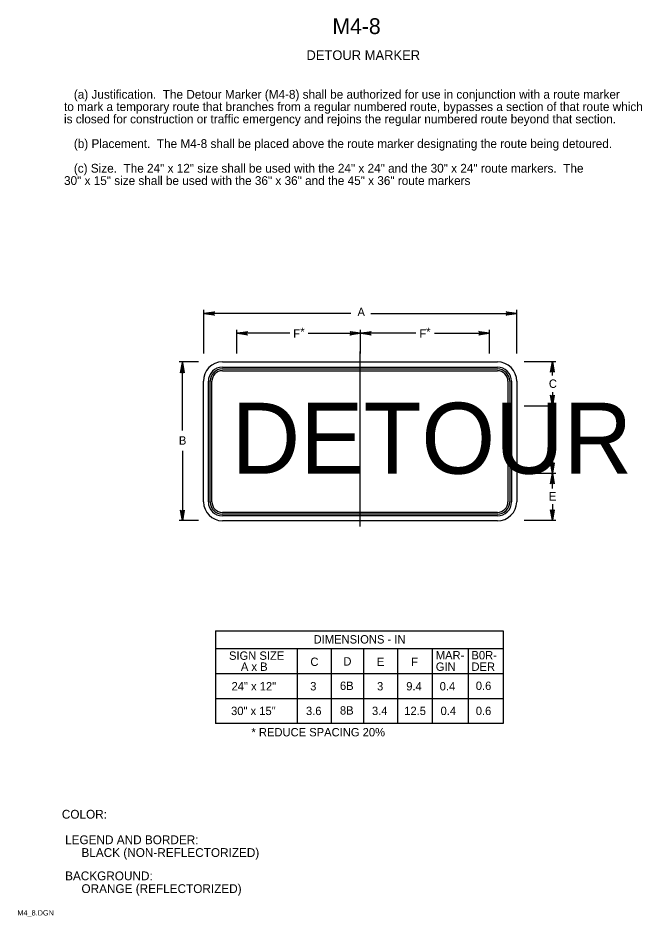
# Model space of a CAD drawing. Extents: x 0.013 to 0.19, y 0.004 to 0.259.
import ezdxf

# ---------------------------------------------------------------- set-up
doc = ezdxf.new("R2010")
doc.units = 0
for name, color, linetype in [('1', 7, 'Continuous'), ('2', 7, 'Continuous'), ('3', 7, 'Continuous')]:
    doc.layers.add(name, color=color, linetype=linetype)

# ---------------------------------------------------------------- blocks, each defined once
blk = doc.blocks.new('RARROW')
at = {"layer": '3'}
for p, q in [((-2.156, 0.285), (-2.2665, 0.384625)), ((-2.2665, 0.384625), (0, 0)), ((0, 0), (-2.2665, -0.379125)), ((-2.156, 0.285), (-2.075625, 0.12075)), ((0, 0), (-2.156, 0.285)), ((-2.14975, -0.2705), (0, 0)), ((-2.075625, 0.12075), (0, 0)), ((0, 0), (-2.074, -0.108)), ((-2.2665, -0.379125), (-2.14975, -0.2705)), ((-2.074, -0.108), (-2.14975, -0.2705))]:
    blk.add_line(p, q, dxfattribs=at)

msp = doc.modelspace()

# ---------------------------------------------------------------- linework, layer by layer
at = {"layer": '3'}
for p, q in [((0.0655, 0.16402), (0.0655, 0.17638)), ((0.15438, 0.16402), (0.15438, 0.17638)), ((0.10725, 0.17538), (0.0655, 0.17538)), ((0.11288, 0.17538), (0.15438, 0.17538)), ((0.07487, 0.16402), (0.07487, 0.17075)), ((0.08987, 0.16975), (0.07487, 0.16975)), ((0.09513, 0.16975), (0.11, 0.16975)), ((0.11, 0.16402), (0.11, 0.17075)), ((0.12575, 0.16975), (0.11, 0.16975)), ((0.131, 0.16975), (0.14663, 0.16975)), ((0.14663, 0.16402), (0.14663, 0.17075)), ((0.10988, 0.11488), (0.10988, 0.16462)), ((0.064, 0.16162), (0.05842, 0.16162)), ((0.05942, 0.14213), (0.05942, 0.16162)), ((0.07075, 0.16162), (0.14887, 0.16162)), ((0.15645, 0.16175), (0.1655, 0.16175)), ((0.1645, 0.15775), (0.1645, 0.16175)), ((0.07075, 0.16012), (0.14887, 0.16012)), ((0.07075, 0.15963), (0.14887, 0.15963)), ((0.07075, 0.15913), (0.14887, 0.15913)), ((0.06538, 0.12187), (0.06538, 0.15612)), ((0.06675, 0.12187), (0.06675, 0.15612)), ((0.06725, 0.12187), (0.06725, 0.15612)), ((0.06775, 0.12187), (0.06775, 0.15612)), ((0.15188, 0.15612), (0.15188, 0.12187)), ((0.15238, 0.15612), (0.15238, 0.12187)), ((0.15288, 0.15612), (0.15288, 0.12187)), ((0.15438, 0.15612), (0.15438, 0.12187)), ((0.1645, 0.153), (0.1645, 0.14913)), ((0.15645, 0.14913), (0.1655, 0.14913)), ((0.1645, 0.14213), (0.1645, 0.14913)), ((0.05942, 0.13637), (0.05942, 0.11662)), ((0.1645, 0.13725), (0.1645, 0.13)), ((0.15645, 0.13), (0.1655, 0.13)), ((0.1645, 0.12563), (0.1645, 0.13)), ((0.1645, 0.12125), (0.1645, 0.11663)), ((0.14887, 0.11888), (0.07075, 0.11888)), ((0.14887, 0.11838), (0.07075, 0.11838)), ((0.14887, 0.11788), (0.07075, 0.11788)), ((0.064, 0.11662), (0.05842, 0.11662)), ((0.14887, 0.1165), (0.07075, 0.1165)), ((0.15645, 0.11663), (0.1655, 0.11663)), ((0.06875, 0.08525), (0.06875, 0.05888)), ((0.06876, 0.08528), (0.15047, 0.08528)), ((0.15047, 0.08528), (0.15047, 0.05891)), ((0.15047, 0.08016), (0.06876, 0.08016)), ((0.09196, 0.08015), (0.09196, 0.05891)), ((0.10163, 0.08013), (0.10163, 0.05888)), ((0.11088, 0.08013), (0.11088, 0.05888)), ((0.1205, 0.08013), (0.1205, 0.05888)), ((0.13031, 0.08015), (0.13031, 0.05891)), ((0.14055, 0.08015), (0.14055, 0.05891)), ((0.15047, 0.07303), (0.06876, 0.07303)), ((0.15047, 0.06591), (0.06876, 0.06591)), ((0.15047, 0.05891), (0.06876, 0.05891))]:
    msp.add_line(p, q, dxfattribs=at)
for centre, radius, start, end in [((0.07081, 0.15619), 0.00544, 90.6585, 180.6585), ((0.14887, 0.15612), 0.0055, 0, 90), ((0.07075, 0.15612), 0.004, 90, 180), ((0.07075, 0.15612), 0.0035, 90, 180), ((0.07075, 0.15612), 0.003, 90, 180), ((0.14887, 0.15612), 0.004, 0, 90), ((0.14887, 0.15612), 0.0035, 0, 90), ((0.14887, 0.15612), 0.003, 0, 90), ((0.07075, 0.12187), 0.00537, 180, 270), ((0.07075, 0.12187), 0.004, 180, 270), ((0.07075, 0.12187), 0.0035, 180, 270), ((0.07075, 0.12187), 0.003, 180, 270), ((0.14887, 0.12187), 0.004, 270, 0), ((0.14887, 0.12187), 0.0035, 270, 0), ((0.14887, 0.12187), 0.003, 270, 0), ((0.14894, 0.12194), 0.00544, 269.3415, 359.3415)]:
    msp.add_arc(centre, radius, start, end, dxfattribs=at)

# ---------------------------------------------------------------- block references
at = {"layer": '3', "xscale": 0.0013236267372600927, "yscale": 0.001309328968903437}
for p, rotation in [((0.0655, 0.17538), 180), ((0.07487, 0.16975), 180), ((0.11, 0.16975), 180), ((0.05938, 0.1615), 90), ((0.1645, 0.16175), 90), ((0.1645, 0.14913), -90), ((0.1645, 0.14913), 90), ((0.1645, 0.13), -90), ((0.1645, 0.13), 90), ((0.05938, 0.1165), -90), ((0.1645, 0.11663), -90)]:
    msp.add_blockref('RARROW', p, dxfattribs=dict(at, rotation=rotation))
for p in [(0.15438, 0.17538), (0.11, 0.16975), (0.14663, 0.16975)]:
    msp.add_blockref('RARROW', p, dxfattribs=at)

# ---------------------------------------------------------------- texts
at = {"layer": '1'}
for s, height, p in [('M4-8', 0.0045, (0.102, 0.25475)), ('DETOUR MARKER', 0.0027503, (0.09463, 0.24738)), ('COLOR:', 0.0025, (0.02513, 0.03188)), (' LEGEND AND BORDER:', 0.0024998, (0.02513, 0.02463)), ('      BLACK (NON-REFLECTORIZED)', 0.0024998, (0.02513, 0.021)), (' BACKGROUND:', 0.0024998, (0.02513, 0.01438)), ('      ORANGE (REFLECTORIZED)', 0.0024998, (0.02513, 0.01075)), ('M4_8.DGN', 0.0015, (0.0125, 0.00438))]:
    msp.add_text(s, height=height, dxfattribs=at).set_placement(p)
at = {"layer": '2'}
for s, height, p in [('   (a) Justification.  The Detour Marker (M4-8) shall be authorized for use in conjunction with a route marker ', 0.00249975, (0.02575, 0.23638)), ('to mark a temporary route that branches from a regular numbered route, bypasses a section of that route which ', 0.00249975, (0.02575, 0.23288)), ('is closed for construction or traffic emergency and rejoins the regular numbered route beyond that section.', 0.00249975, (0.02575, 0.22938)), ('   (b) Placement.  The M4-8 shall be placed above the route marker designating the route being detoured.', 0.00249975, (0.02575, 0.22238)), ('   (c) Size.  The 24" x 12" size shall be used with the 24" x 24" and the 30" x 24" route markers.  The  ', 0.00249975, (0.02575, 0.21538)), ('30" x 15" size shall be used with the 36" x 36" and the 45" x 36" route markers', 0.0024998, (0.02575, 0.21188))]:
    msp.add_text(s, height=height, dxfattribs=at).set_placement(p)
at = {"layer": '3'}
for s, height, p in [('A', 0.00238, (0.10912, 0.17463)), ('*', 0.00238, (0.09287, 0.169)), ('*', 0.00238, (0.12862, 0.169)), ('F ', 0.002375, (0.09087, 0.1685)), ('F ', 0.002375, (0.12675, 0.1685)), ('C', 0.00238, (0.1635, 0.15425)), ('DETOUR', 0.020155, (0.07337, 0.12987)), ('B', 0.00238, (0.05838, 0.13812)), ('D', 0.00238, (0.1635, 0.1385)), ('E', 0.00238, (0.1635, 0.12225)), ('DIMENSIONS - IN', 0.0023752, (0.09666, 0.08163)), ('SIGN SIZE', 0.002375, (0.07262, 0.077)), ('MAR-', 0.002375, (0.13137, 0.07712)), ('B0R-', 0.002375, (0.1415, 0.07712)), ('C', 0.00238, (0.09575, 0.07525)), ('D', 0.00238, (0.10512, 0.07537)), ('E', 0.00238, (0.11463, 0.07525)), ('F', 0.00238, (0.12437, 0.07525)), ('A x B', 0.002375, (0.076, 0.07387)), ('GIN', 0.002375, (0.13137, 0.07387)), ('DER', 0.002375, (0.1415, 0.07387)), ('24" x 12"', 0.002375, (0.07334, 0.06831)), ('3', 0.00238, (0.09568, 0.06831)), ('6B', 0.002375, (0.10414, 0.06844)), ('3', 0.00238, (0.11468, 0.06831)), ('9.4', 0.002375, (0.12298, 0.06831)), ('0.4', 0.002375, (0.13248, 0.06831)), ('0.6', 0.002375, (0.14274, 0.06844)), ('8B', 0.002375, (0.10414, 0.06144)), ('30" x 15"', 0.002375, (0.07321, 0.06131)), ('3.6', 0.002375, (0.09449, 0.06131)), ('3.4', 0.002375, (0.11323, 0.06131)), ('12.5', 0.002375, (0.1224, 0.06131)), ('0.4', 0.002375, (0.13273, 0.06131)), ('0.6', 0.002375, (0.14274, 0.06131)), ('* REDUCE SPACING 20%', 0.0023752, (0.079, 0.05525))]:
    msp.add_text(s, height=height, dxfattribs=at).set_placement(p)

doc.saveas('drawing.dxf')
